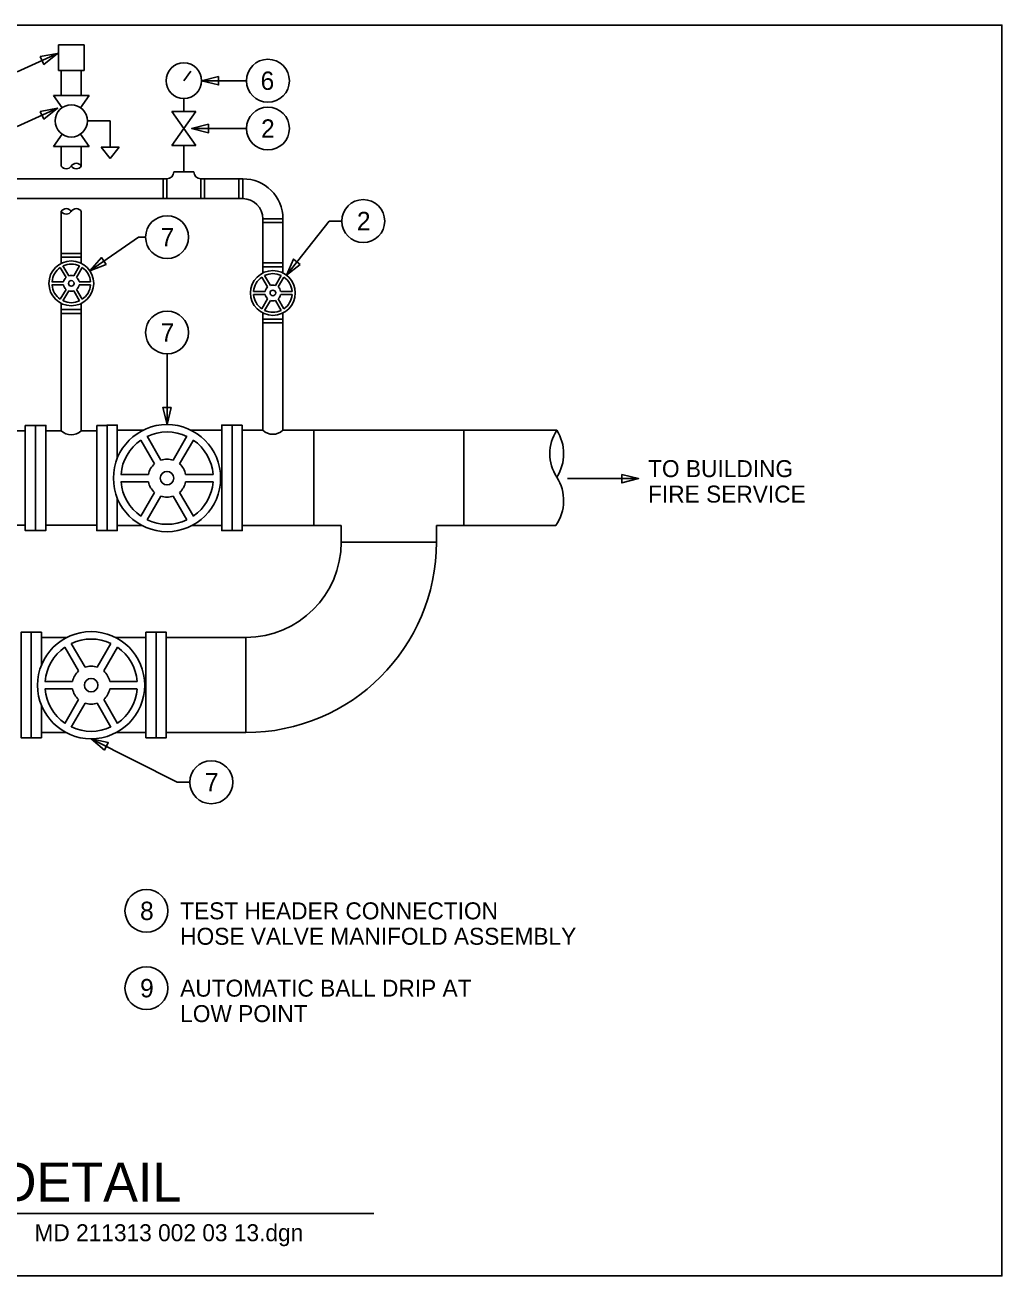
# Model space of a CAD drawing. Extents: x 10442.9 to 10533.9, y 10030 to 10079.1.
# Drawn here: x 10495.58 to 10533.95, y 10029.98 to 10079.12 of the extents above; entities that cross this region are included whole.
import ezdxf

# ---------------------------------------------------------------- set-up
doc = ezdxf.new("R2010")
doc.units = 0
for name, color, linetype in [('G-ANNO-CELL', 7, 'Continuous'), ('G-ANNO-NPLT', 7, 'Continuous'), ('G-ANNO-SYMB', 7, 'Continuous'), ('G-DETL-LINE', 7, 'Continuous'), ('G-DETL-TEXT', 7, 'Continuous')]:
    doc.layers.add(name, color=color, linetype=linetype)

msp = doc.modelspace()

# ---------------------------------------------------------------- linework, layer by layer
at = {"layer": 'G-ANNO-CELL'}
msp.add_line((10467.62, 10032.437), (10509.274, 10032.437), dxfattribs=at)
at = {"layer": 'G-ANNO-NPLT'}
msp.add_lwpolyline([(10488.447, 10029.978), (10488.447, 10079.12), (10533.947, 10079.12), (10533.947, 10029.978)], close=True, dxfattribs=at)
at = {"layer": 'G-ANNO-SYMB'}
for centre in [(10505.117, 10076.932), (10505.117, 10075.054), (10508.862, 10071.42), (10501.156, 10070.787), (10501.156, 10067.041), (10502.895, 10049.374), (10500.348, 10044.322), (10500.348, 10041.285)]:
    msp.add_circle(centre, 0.843, dxfattribs=at)
at = {"layer": 'G-DETL-LINE'}
for p, q in [((10496.896, 10078.348), (10496.896, 10077.329)), ((10496.896, 10078.348), (10497.896, 10078.348)), ((10497.896, 10078.348), (10497.896, 10077.329)), ((10496.856, 10078.002), (10495.267, 10077.283)), ((10496.896, 10077.329), (10497.896, 10077.329)), ((10497.003, 10076.358), (10497.003, 10077.329)), ((10497.789, 10076.358), (10497.789, 10077.329)), ((10501.816, 10076.932), (10502.092, 10077.312)), ((10502.516, 10076.932), (10504.274, 10076.932)), ((10496.693, 10076.358), (10498.099, 10076.358)), ((10497.034, 10075.871), (10496.693, 10076.358)), ((10498.099, 10076.358), (10497.758, 10075.871)), ((10501.816, 10076.232), (10501.816, 10075.728)), ((10496.856, 10075.849), (10495.267, 10075.13)), ((10502.285, 10074.389), (10501.347, 10075.728)), ((10501.347, 10075.728), (10502.285, 10075.728)), ((10502.285, 10075.728), (10501.347, 10074.389)), ((10498.028, 10075.353), (10498.923, 10075.353)), ((10498.923, 10075.353), (10498.923, 10074.319)), ((10497.034, 10074.836), (10496.693, 10074.349)), ((10498.099, 10074.349), (10497.758, 10074.836)), ((10502.119, 10075.054), (10503.774, 10075.054)), ((10504.274, 10075.054), (10503.774, 10075.054)), ((10496.693, 10074.349), (10498.099, 10074.349)), ((10497.003, 10073.579), (10497.003, 10074.349)), ((10497.789, 10073.579), (10497.789, 10074.349)), ((10498.566, 10074.319), (10499.279, 10074.319)), ((10498.923, 10073.871), (10498.566, 10074.319)), ((10498.923, 10073.871), (10499.279, 10074.319)), ((10501.347, 10074.389), (10502.285, 10074.389)), ((10501.816, 10074.389), (10501.816, 10073.349)), ((10501.423, 10073.349), (10502.209, 10073.349)), ((10501.153, 10073.079), (10491.106, 10073.079)), ((10501.006, 10073.079), (10501.006, 10072.292)), ((10501.153, 10073.079), (10501.153, 10072.292)), ((10504.132, 10073.079), (10502.48, 10073.079)), ((10502.48, 10073.079), (10502.48, 10072.292)), ((10502.626, 10073.079), (10502.626, 10072.292)), ((10503.982, 10072.299), (10503.982, 10073.079)), ((10504.132, 10072.299), (10504.132, 10073.079)), ((10504.132, 10072.299), (10491.084, 10072.299)), ((10497.003, 10069.758), (10497.003, 10071.799)), ((10497.789, 10069.758), (10497.789, 10071.799)), ((10504.92, 10069.382), (10504.92, 10071.511)), ((10504.92, 10071.511), (10505.709, 10071.511)), ((10504.92, 10071.361), (10505.709, 10071.361)), ((10505.707, 10069.382), (10505.707, 10071.511)), ((10505.843, 10069.298), (10507.519, 10071.42)), ((10508.019, 10071.42), (10507.519, 10071.42)), ((10498.123, 10069.466), (10500.036, 10070.787)), ((10500.314, 10070.787), (10500.036, 10070.787)), ((10497.003, 10070.149), (10497.789, 10070.149)), ((10497.003, 10070.003), (10497.789, 10070.003)), ((10504.92, 10069.774), (10505.707, 10069.774)), ((10497.19, 10069.205), (10496.964, 10069.597)), ((10497.296, 10069.266), (10497.07, 10069.658)), ((10497.722, 10069.658), (10497.496, 10069.266)), ((10497.828, 10069.597), (10497.602, 10069.205)), ((10505.107, 10068.829), (10504.881, 10069.221)), ((10504.92, 10069.627), (10505.707, 10069.627)), ((10505.213, 10068.891), (10504.987, 10069.282)), ((10505.64, 10069.282), (10505.413, 10068.891)), ((10505.746, 10069.221), (10505.519, 10068.829)), ((10497.09, 10069.033), (10496.638, 10069.033)), ((10497.09, 10068.909), (10496.638, 10068.909)), ((10497.19, 10068.737), (10496.964, 10068.345)), ((10497.828, 10068.345), (10497.602, 10068.737)), ((10498.154, 10069.033), (10497.702, 10069.033)), ((10498.154, 10068.909), (10497.702, 10068.909)), ((10497.296, 10068.675), (10497.07, 10068.284)), ((10497.722, 10068.284), (10497.496, 10068.675)), ((10505.008, 10068.657), (10504.555, 10068.657)), ((10505.008, 10068.533), (10504.555, 10068.533)), ((10505.107, 10068.361), (10504.881, 10067.969)), ((10505.213, 10068.3), (10504.987, 10067.908)), ((10505.64, 10067.908), (10505.413, 10068.3)), ((10505.746, 10067.969), (10505.519, 10068.361)), ((10506.072, 10068.657), (10505.619, 10068.657)), ((10506.072, 10068.533), (10505.619, 10068.533)), ((10497.003, 10063.184), (10497.003, 10068.184)), ((10497.003, 10067.939), (10497.789, 10067.939)), ((10497.003, 10067.792), (10497.789, 10067.792)), ((10497.789, 10063.184), (10497.789, 10068.184)), ((10504.92, 10063.2), (10504.92, 10067.808)), ((10505.707, 10063.2), (10505.707, 10067.808)), ((10504.92, 10067.563), (10505.707, 10067.563)), ((10504.92, 10067.417), (10505.707, 10067.417)), ((10501.156, 10063.425), (10501.156, 10066.199)), ((10496.999, 10063.393), (10497.003, 10063.393)), ((10494.043, 10063.184), (10495.579, 10063.184)), ((10496.399, 10063.184), (10497.003, 10063.184)), ((10497.789, 10063.184), (10498.393, 10063.184)), ((10499.203, 10063.2), (10500.21, 10063.2)), ((10500.917, 10062.027), (10500.376, 10062.964)), ((10501.936, 10062.964), (10501.395, 10062.027)), ((10502.103, 10063.2), (10503.307, 10063.2)), ((10504.108, 10063.2), (10504.92, 10063.2)), ((10504.917, 10063.2), (10504.92, 10063.2)), ((10505.707, 10063.2), (10506.922, 10063.2)), ((10506.922, 10063.2), (10506.922, 10059.46)), ((10512.807, 10063.2), (10506.922, 10063.2)), ((10512.807, 10063.2), (10516.46, 10063.2)), ((10512.807, 10063.2), (10512.807, 10059.46)), ((10500.663, 10061.881), (10500.122, 10062.818)), ((10502.19, 10062.818), (10501.649, 10061.881)), ((10500.425, 10061.469), (10499.342, 10061.469)), ((10502.97, 10061.469), (10501.887, 10061.469)), ((10500.425, 10061.171), (10499.342, 10061.171)), ((10502.97, 10061.171), (10501.887, 10061.171)), ((10500.663, 10060.759), (10500.122, 10059.822)), ((10500.917, 10060.613), (10500.376, 10059.676)), ((10501.936, 10059.676), (10501.395, 10060.613)), ((10502.19, 10059.822), (10501.649, 10060.759)), ((10494.043, 10059.471), (10495.579, 10059.471)), ((10496.399, 10059.471), (10498.393, 10059.471)), ((10499.203, 10059.46), (10500.172, 10059.46)), ((10502.14, 10059.46), (10503.307, 10059.46)), ((10504.108, 10059.46), (10506.922, 10059.46)), ((10507.995, 10059.46), (10506.922, 10059.46)), ((10507.995, 10059.46), (10507.995, 10058.806)), ((10512.807, 10059.46), (10511.734, 10059.46)), ((10511.734, 10059.46), (10511.734, 10058.806)), ((10512.807, 10059.46), (10516.422, 10059.46)), ((10511.734, 10058.806), (10507.995, 10058.806)), ((10496.222, 10055.066), (10497.229, 10055.066)), ((10499.121, 10055.066), (10500.326, 10055.066)), ((10501.127, 10055.066), (10504.255, 10055.066)), ((10504.255, 10055.066), (10504.255, 10051.326)), ((10497.682, 10053.747), (10497.141, 10054.684)), ((10497.936, 10053.893), (10497.395, 10054.83)), ((10498.955, 10054.83), (10498.414, 10053.893)), ((10499.209, 10054.684), (10498.668, 10053.747)), ((10497.444, 10053.335), (10496.361, 10053.335)), ((10497.444, 10053.037), (10496.361, 10053.037)), ((10499.989, 10053.335), (10498.906, 10053.335)), ((10499.989, 10053.037), (10498.906, 10053.037)), ((10497.682, 10052.625), (10497.141, 10051.688)), ((10499.209, 10051.688), (10498.668, 10052.625)), ((10497.936, 10052.479), (10497.395, 10051.542)), ((10498.955, 10051.542), (10498.414, 10052.479)), ((10496.222, 10051.325), (10497.191, 10051.325)), ((10498.175, 10051.081), (10501.553, 10049.374)), ((10499.159, 10051.325), (10500.326, 10051.325)), ((10501.127, 10051.325), (10504.255, 10051.325)), ((10502.053, 10049.374), (10501.553, 10049.374))]:
    msp.add_line(p, q, dxfattribs=at)
for points in [[(10496.18, 10077.879), (10496.856, 10078.002), (10496.318, 10077.575)], [(10503.183, 10077.099), (10502.516, 10076.932), (10503.183, 10076.765)], [(10496.18, 10075.726), (10496.856, 10075.849), (10496.318, 10075.422)], [(10502.785, 10075.22), (10502.119, 10075.054), (10502.785, 10074.887)], [(10498.767, 10069.707), (10498.123, 10069.466), (10498.577, 10069.982)], [(10506.387, 10069.717), (10505.843, 10069.298), (10506.125, 10069.924)], [(10501.323, 10064.091), (10501.156, 10063.425), (10500.989, 10064.091)], [(10495.579, 10063.393), (10495.989, 10063.393), (10495.989, 10059.267), (10495.579, 10059.267)], [(10495.989, 10063.393), (10496.399, 10063.393), (10496.399, 10059.267), (10495.989, 10059.267)], [(10498.393, 10063.394), (10498.803, 10063.394), (10498.803, 10059.257), (10498.393, 10059.257)], [(10503.708, 10063.402), (10503.307, 10063.402), (10503.307, 10059.257), (10503.708, 10059.257)], [(10504.108, 10063.402), (10503.708, 10063.402), (10503.708, 10059.257), (10504.108, 10059.257)], [(10500.726, 10055.268), (10500.326, 10055.268), (10500.326, 10051.123), (10500.726, 10051.123)], [(10498.695, 10050.632), (10498.175, 10051.081), (10498.845, 10050.929)]]:
    msp.add_lwpolyline(points, close=True, dxfattribs=at)
for points in [[(10498.803, 10063.402), (10498.803, 10059.257), (10499.203, 10059.257), (10499.203, 10060.535)], [(10499.203, 10062.105), (10499.203, 10063.402), (10498.803, 10063.402), (10498.803, 10062.041)], [(10495.822, 10053.907), (10495.822, 10055.268), (10495.421, 10055.268), (10495.421, 10051.123), (10495.822, 10051.123), (10495.822, 10052.465)], [(10495.822, 10055.268), (10495.822, 10051.123), (10496.222, 10051.123), (10496.222, 10052.401)], [(10496.222, 10053.971), (10496.222, 10055.268), (10495.822, 10055.268), (10495.822, 10053.907)], [(10500.726, 10053.907), (10500.726, 10055.268), (10501.127, 10055.268), (10501.127, 10051.123), (10500.726, 10051.123), (10500.726, 10052.465)]]:
    msp.add_lwpolyline(points, dxfattribs=at)
for centre, radius in [((10501.816, 10076.932), 0.7), ((10497.396, 10075.353), 0.632), ((10497.396, 10068.971), 0.88), ((10505.313, 10068.595), 0.88), ((10497.396, 10068.971), 0.111), ((10505.313, 10068.595), 0.111), ((10501.156, 10061.32), 2.105), ((10501.156, 10061.32), 0.265), ((10498.175, 10053.186), 2.105), ((10498.175, 10053.186), 0.265)]:
    msp.add_circle(centre, radius, dxfattribs=at)
for centre, radius, start, end in [((10497.592, 10073.457), 0.231, 31.7961, 148.2039), ((10497.199, 10073.701), 0.231, 211.7961, 328.2039), ((10497.592, 10073.701), 0.231, 211.7961, 328.2039), ((10501.153, 10073.349), 0.27, 270, 0), ((10502.48, 10073.349), 0.27, 180, 270), ((10504.132, 10071.502), 1.577, 0.327, 90), ((10504.132, 10071.511), 0.788, 0, 90), ((10497.199, 10071.678), 0.231, 31.7961, 148.2039), ((10497.199, 10071.921), 0.231, 211.7961, 328.2039), ((10497.592, 10071.678), 0.231, 31.7961, 148.2039), ((10497.396, 10068.971), 0.758, 64.6295, 115.3705), ((10497.396, 10068.971), 0.758, 124.6295, 175.2858), ((10497.396, 10068.971), 0.312, 71.3127, 108.6873), ((10497.396, 10068.971), 0.758, 4.7142, 55.3705), ((10505.313, 10068.595), 0.758, 124.6295, 175.2858), ((10505.313, 10068.595), 0.758, 64.6295, 115.3705), ((10505.313, 10068.595), 0.758, 4.7142, 55.3705), ((10497.396, 10068.971), 0.758, 184.7142, 235.3705), ((10497.396, 10068.971), 0.312, 131.3127, 168.4779), ((10497.396, 10068.971), 0.312, 191.5221, 228.6873), ((10497.396, 10068.971), 0.312, 11.5221, 48.6873), ((10497.396, 10068.971), 0.312, 311.3127, 348.4779), ((10497.396, 10068.971), 0.758, 304.6295, 355.2858), ((10505.313, 10068.595), 0.312, 131.3127, 168.4779), ((10505.313, 10068.595), 0.312, 71.3127, 108.6873), ((10505.313, 10068.595), 0.312, 11.5221, 48.6873), ((10497.396, 10068.971), 0.758, 244.6295, 295.3705), ((10497.396, 10068.971), 0.312, 251.3127, 288.6873), ((10505.313, 10068.595), 0.758, 184.7142, 235.3705), ((10505.313, 10068.595), 0.312, 191.5221, 228.6873), ((10505.313, 10068.595), 0.312, 251.3127, 288.6873), ((10505.313, 10068.595), 0.312, 311.3127, 348.4779), ((10505.313, 10068.595), 0.758, 304.6295, 355.2858), ((10505.313, 10068.595), 0.758, 244.6295, 295.3705), ((10497.396, 10063.597), 0.57, 226.3681, 313.6319), ((10501.156, 10061.32), 1.814, 64.6295, 115.3705), ((10505.313, 10063.613), 0.57, 226.3681, 313.6319), ((10517.879, 10062.279), 1.691, 147.0136, 212.9864), ((10515.042, 10062.279), 1.691, 327.0136, 32.9864), ((10501.156, 10061.32), 1.814, 124.6295, 175.2858), ((10501.156, 10061.32), 1.814, 4.7142, 55.3705), ((10501.156, 10061.32), 0.746, 131.3127, 168.4779), ((10501.156, 10061.32), 0.746, 71.3127, 108.6873), ((10501.156, 10061.32), 0.746, 11.5221, 48.6873), ((10515.042, 10060.437), 1.691, 324.6797, 32.9864), ((10501.156, 10061.32), 1.814, 184.7142, 235.3705), ((10501.156, 10061.32), 0.746, 191.5221, 228.6873), ((10501.156, 10061.32), 0.746, 311.3127, 348.4779), ((10501.156, 10061.32), 1.814, 304.6295, 355.2858), ((10501.156, 10061.32), 0.746, 251.3127, 288.6873), ((10501.156, 10061.32), 1.814, 244.6295, 295.3705), ((10504.255, 10058.806), 3.74, 270, 360), ((10504.255, 10058.806), 7.479, 270, 360), ((10498.175, 10053.186), 1.814, 64.6295, 115.3705), ((10498.175, 10053.186), 1.814, 124.6295, 175.2858), ((10498.175, 10053.186), 1.814, 4.7142, 55.3705), ((10498.175, 10053.186), 0.746, 131.3127, 168.4779), ((10498.175, 10053.186), 0.746, 71.3127, 108.6873), ((10498.175, 10053.186), 0.746, 11.5221, 48.6873), ((10498.175, 10053.186), 1.814, 184.7142, 235.3705), ((10498.175, 10053.186), 0.746, 191.5221, 228.6873), ((10498.175, 10053.186), 0.746, 311.3127, 348.4779), ((10498.175, 10053.186), 1.814, 304.6295, 355.2858), ((10498.175, 10053.186), 0.746, 251.3127, 288.6873), ((10498.175, 10053.186), 1.814, 244.6295, 295.3705)]:
    msp.add_arc(centre, radius, start, end, dxfattribs=at)
at = {"layer": 'G-DETL-TEXT'}
msp.add_line((10519.678, 10061.301), (10516.88, 10061.301), dxfattribs=at)
msp.add_lwpolyline([(10519.012, 10061.468), (10519.678, 10061.301), (10519.012, 10061.135)], close=True, dxfattribs=at)

# ---------------------------------------------------------------- texts
at = {"layer": 'G-ANNO-CELL'}
msp.add_text('FIRE PUMP SYSTEM DETAIL', height=1.53173, dxfattribs=at).set_placement((10473.838, 10032.904))
at = {"layer": 'G-ANNO-SYMB'}
for s, p in [('6', (10504.83, 10076.572)), ('2', (10504.849, 10074.693)), ('2', (10508.613, 10071.059)), ('7', (10500.903, 10070.427)), ('7', (10500.903, 10066.681)), ('7', (10502.643, 10049.014)), ('8', (10500.096, 10043.961)), ('9', (10500.098, 10040.925))]:
    msp.add_text(s, height=0.721, dxfattribs=at).set_placement(p)
at = {"layer": 'G-DETL-TEXT'}
for s, height, p in [('TO BUILDING', 0.66667, (10520.048, 10061.36)), ('FIRE SERVICE', 0.66667, (10520.048, 10060.36)), ('TEST HEADER CONNECTION', 0.66667, (10501.672, 10043.989)), ('HOSE VALVE MANIFOLD ASSEMBLY', 0.66667, (10501.672, 10042.989)), ('AUTOMATIC BALL DRIP AT', 0.66667, (10501.672, 10040.952)), ('LOW POINT', 0.6667, (10501.672, 10039.952)), ('MD 211313 002 03 13.dgn', 0.66667, (10495.949, 10031.345))]:
    msp.add_text(s, height=height, dxfattribs=at).set_placement(p)

doc.saveas('drawing.dxf')
